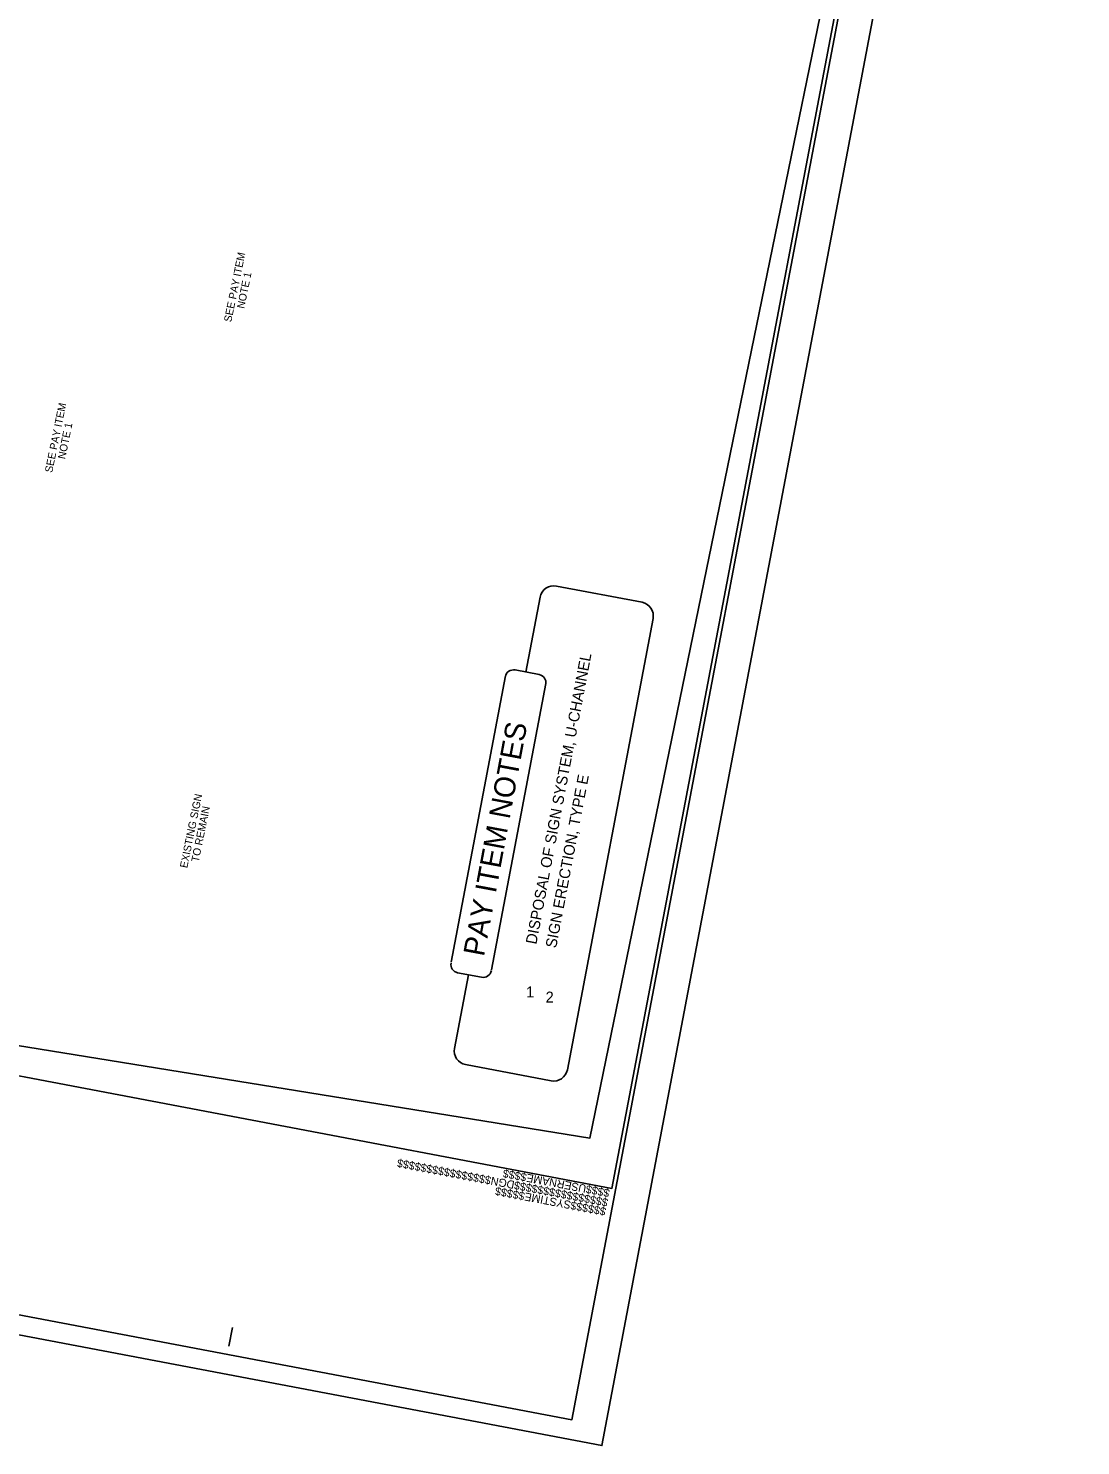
# Model space of a CAD drawing. Extents: x 1615681 to 1617075, y 899309 to 901168.
# Drawn here: x 1616385 to 1617075, y 899309 to 900239 of the extents above; entities that cross this region are included whole.
import ezdxf

# ---------------------------------------------------------------- set-up
doc = ezdxf.new("R2010")
doc.units = 0
for name, color, linetype in [('CTL Primary Horizontal and Vertical CELL', 7, 'Continuous'), ('CTL Primary Horizontal and Vertical Cogo Number', 7, 'Continuous'), ('CTL Secondary Horizontal and Vertical CELL', 7, 'Continuous'), ('Default', 7, 'Continuous'), ('Exist DTM Crownline Cogo Number', 7, 'Continuous'), ('Exist Utilities Sanitary Sewer Manhole Cogo Number', 7, 'Continuous')]:
    doc.layers.add(name, color=color, linetype=linetype)

msp = doc.modelspace()

# ---------------------------------------------------------------- linework, layer by layer
at = {"layer": 'CTL Primary Horizontal and Vertical CELL'}
msp.add_lwpolyline([(1616015.87, 901159.82), (1615705.01, 899522.57), (1616741.59, 899325.76), (1617052.45, 900963.01)], close=True, dxfattribs=at)
at = {"layer": 'CTL Primary Horizontal and Vertical Cogo Number'}
msp.add_lwpolyline([(1615994.65, 901168.43), (1615680.53, 899513.99), (1616761.22, 899308.8), (1617075.34, 900963.24)], close=True, dxfattribs=at)
at = {"layer": 'CTL Secondary Horizontal and Vertical CELL'}
msp.add_line((1616516.6, 899374.08), (1616518.93, 899386.36), dxfattribs=at)
msp.add_lwpolyline([(1616016.04, 901147.07), (1615736.24, 899673.39), (1616767.81, 899477.53), (1617047.61, 900951.21)], close=True, dxfattribs=at)
at = {"layer": 'Exist DTM Crownline Cogo Number'}
msp.add_lwpolyline([(1616176.29, 901060.7), (1617032.97, 900874.07), (1616753.23, 899510.43), (1615915.8, 899646.19), (1615751.76, 899738.03), (1615999.36, 900929.08), (1616157.93, 900902)], close=True, dxfattribs=at)
at = {"layer": 'Exist Utilities Sanitary Sewer Manhole Cogo Number'}
for p, q in [((1616787.59, 899862.07), (1616731.39, 899872.74)), ((1616711.42, 899816.33), (1616720.76, 899865.51)), ((1616738.61, 899555.37), (1616794.83, 899851.44)), ((1616720.06, 899814.69), (1616704.32, 899817.68)), ((1616664.55, 899569.44), (1616673.71, 899617.71)), ((1616682.35, 899616.07), (1616666.61, 899619.06)), ((1616727.99, 899548.14), (1616671.78, 899558.81))]:
    msp.add_line(p, q, dxfattribs=at)
for points in [[(1616662.36, 899625.89), (1616698.03, 899813.79)], [(1616688.81, 899620.87), (1616724.49, 899808.76)]]:
    msp.add_lwpolyline(points, dxfattribs=at)
for centre, radius, start, end in [((1616729.69, 899863.81), 9.09, 79.24937, 169.24937), ((1616785.9, 899853.14), 9.09, 349.24937, 79.24937), ((1616703.3, 899812.32), 5.45, 79.24937, 169.24937), ((1616719.05, 899809.33), 5.45, 349.24937, 79.24937), ((1616667.63, 899624.42), 5.45, 169.24937, 259.24937), ((1616683.37, 899621.43), 5.45, 259.24937, 349.24937), ((1616673.48, 899567.74), 9.09, 169.24937, 259.24937), ((1616729.68, 899557.07), 9.09, 259.24937, 349.24937)]:
    msp.add_arc(centre, radius, start, end, dxfattribs=at)

# ---------------------------------------------------------------- texts
at = {"layer": 'CTL Secondary Horizontal and Vertical CELL'}
for s, p in [('$$$$$$$$$$$$$$$$DGN$$$$$$$$$$$$$$$$', (1616765.64, 899470.67)), ('$$$$USERNAME$$$$', (1616766.72, 899476.87)), ('$$$$$$SYSTIME$$$$$', (1616764.32, 899464.76))]:
    msp.add_text(s, height=5.25, rotation=169.24937, dxfattribs=at).set_placement(p)
at = {"layer": 'Default'}
for s, height, rotation, p in [('SEE PAY ITEM', 5, 78.45796, (1616518.1, 900045.61)), ('NOTE 1', 5, 78.45796, (1616526.6, 900054.46)), ('SEE PAY ITEM', 5, 78.45796, (1616400.62, 899946.85)), ('NOTE 1', 5, 78.45796, (1616409.12, 899955.71)), ('DISPOSAL OF SIGN SYSTEM, U-CHANNEL', 7.1994, 79.24937, (1616718.26, 899637.32)), ('PAY ITEM NOTES', 13.8661, 79.43161, (1616683.85, 899629.22)), ('SIGN ERECTION, TYPE E', 7.1994, 79.24937, (1616731.24, 899634.85)), ('EXISTING SIGN', 5, 78.45796, (1616489.21, 899687.42)), ('TO REMAIN', 5, 78.45796, (1616496.7, 899691.35)), ('1', 7.2, 359.97341, (1616711.51, 899602.89)), ('2', 7.2, 359.97341, (1616724.31, 899599.46))]:
    msp.add_text(s, height=height, rotation=rotation, dxfattribs=at).set_placement(p)

doc.saveas('drawing.dxf')
